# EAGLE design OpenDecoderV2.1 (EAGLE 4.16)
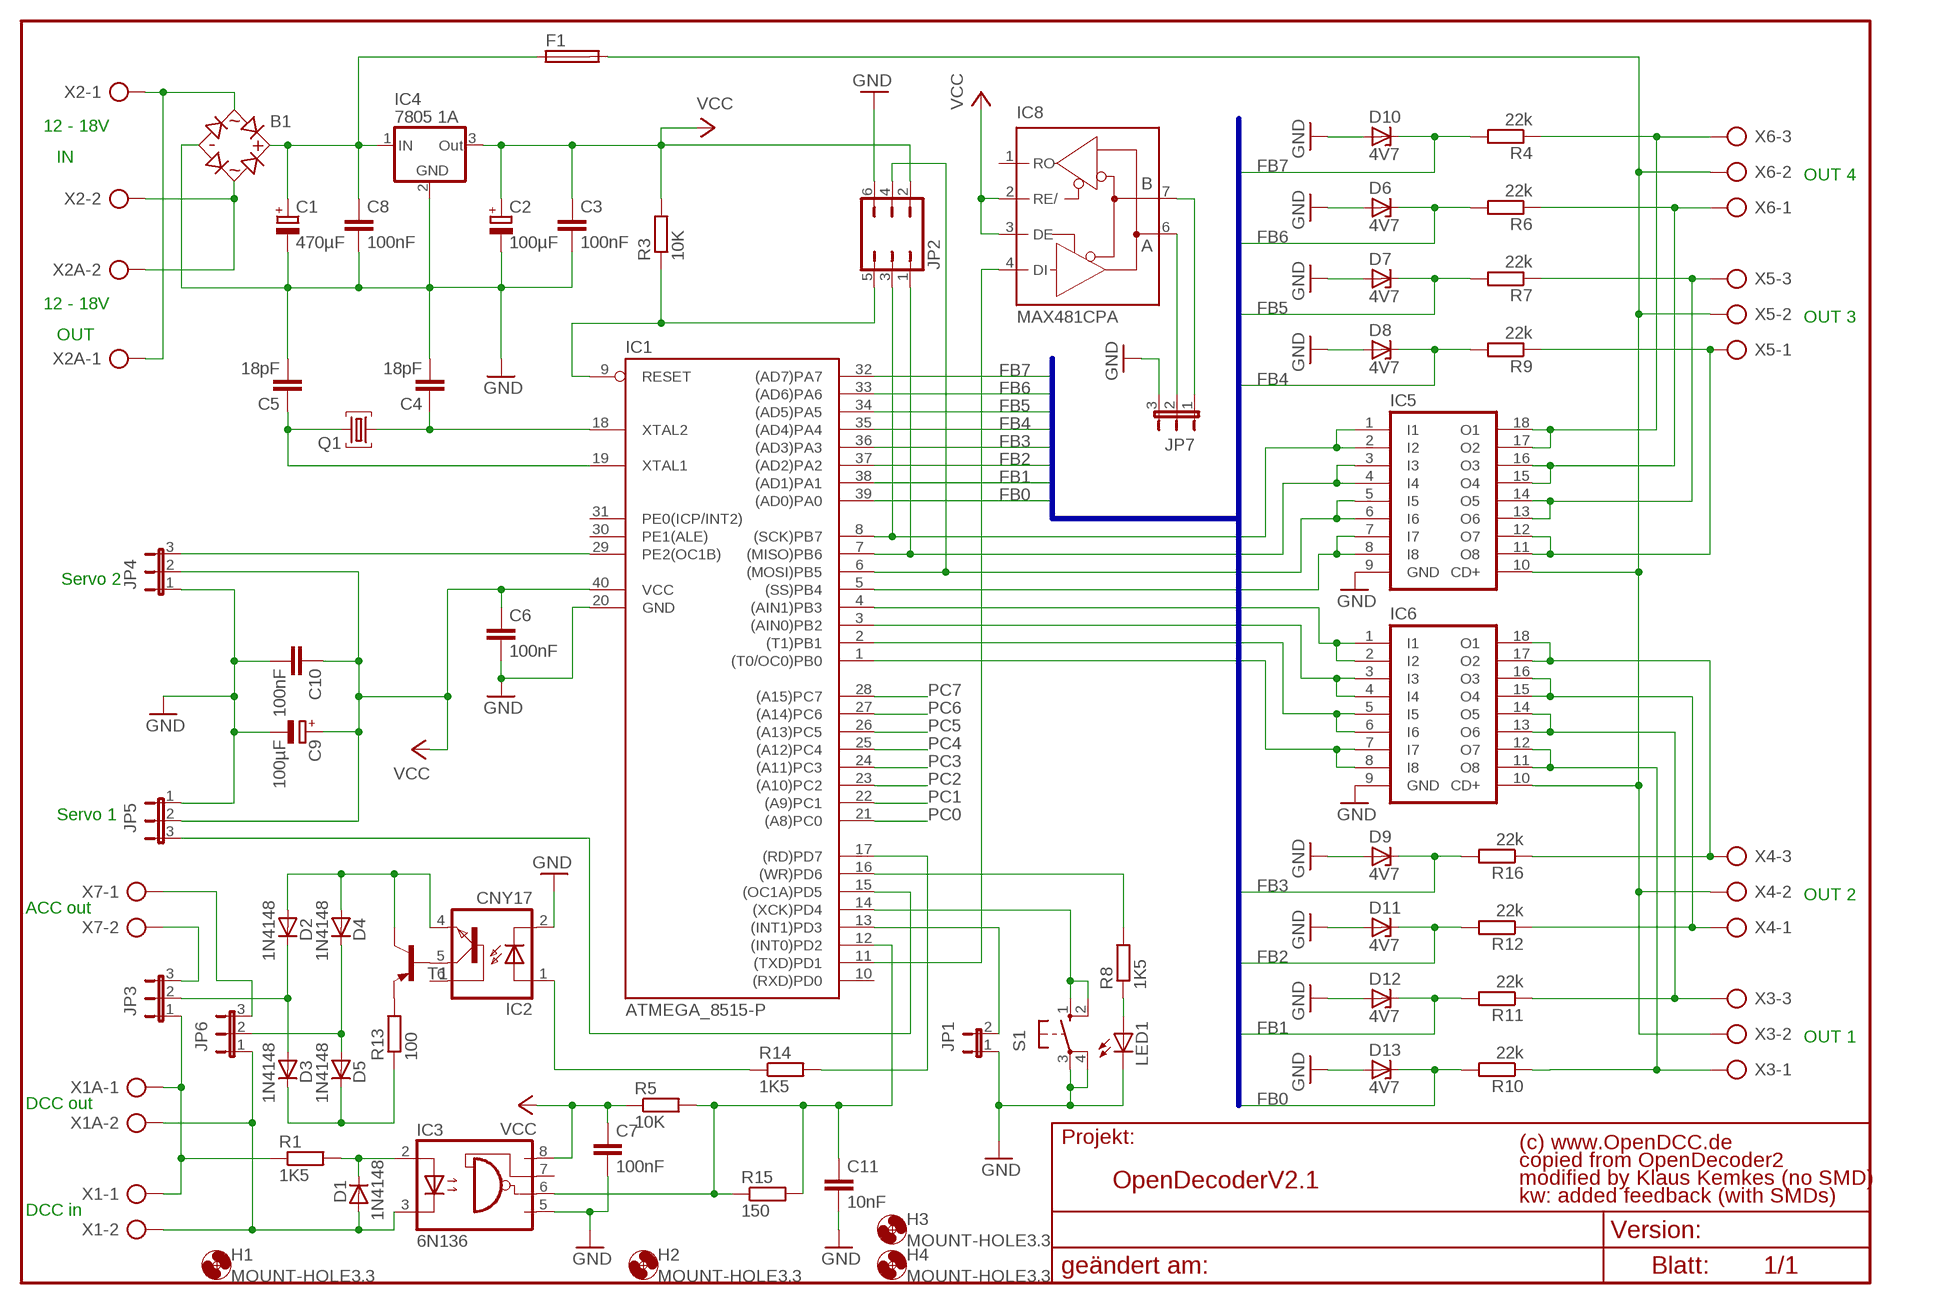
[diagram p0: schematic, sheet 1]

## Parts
B1  1,5A_RUND  [RB1A]
C1  470µF  ELKO-5-10.5-RADIAL  [R5-10,5]
C2  100µF  ELKO-2.5-7--RADIAL  [R2.5-7]
C3  100nF  KERAMIK5/4.5  [K5]
C4  18pF  KERAMIK2.5/4  [K2,5]
C5  18pF  KERAMIK2.5/4  [K2,5]
C6  100nF  KERAMIK5/4.5  [K5]
C7  100nF  KERAMIK5/4.5  [K5]
C8  100nF  KERAMIK5/4.5  [K5]
C9  100µF  ELKO-2.5-7--RADIAL  [R2.5-7]
C10  100nF  KERAMIK2.5/4  [K2,5]
C11  10nF  KERAMIK5/4.5  [K5]
D1  1N4148  1N414810MM  [DO35-10]
D2  1N4148  1N41487,5MM  [DO35-7]
D3  1N4148  1N41487,5MM  [DO35-7]
D4  1N4148  1N41487,5MM  [DO35-7]
D5  1N4148  1N41487,5MM  [DO35-7]
D6  4V7  ZENER-DIODESOD80C  [SOD80C]
D7  4V7  ZENER-DIODESOD80C  [SOD80C]
D8  4V7  ZENER-DIODESOD80C  [SOD80C]
D9  4V7  ZENER-DIODESOD80C  [SOD80C]
D10  4V7  ZENER-DIODESOD80C  [SOD80C]
D11  4V7  ZENER-DIODESOD80C  [SOD80C]
D12  4V7  ZENER-DIODESOD80C  [SOD80C]
D13  4V7  ZENER-DIODESOD80C  [SOD80C]
F1  TE5A  [TE5]
H1  MOUNT-HOLE3.3  [3,3]
H2  MOUNT-HOLE3.3  [3,3]
H3  MOUNT-HOLE3.3  [3,3]
H4  MOUNT-HOLE3.3  [3,3]
IC1  ATMEGA_8515-P  [DIL40]
IC2  CNY17  [DIL06]
IC3  6N136  6N137  [DIL08]
IC4  7805 1A  78S15  [TO220STEHEND]
IC5  ULN2803A  [DIL18]
IC6  ULN2803A  [DIL18]
IC8  MAX481CPA  [DIL08]
JP1  STIFTLEISTE_2POL  [STIFTLEISTE_2POL]
JP2  STIFTLEISTE_3POL_2REIHIG  [STIFTLEISTE_3POL_2REIHIG]
JP3  STIFTLEISTE_3POL  [STIFTLEISTE_3POL]
JP4  Servo2  STIFTLEISTE_3POL  [STIFTLEISTE_3POL]
JP5  Servo1  STIFTLEISTE_3POL  [STIFTLEISTE_3POL]
JP6  STIFTLEISTE_3POL  [STIFTLEISTE_3POL]
JP7  STIFTLEISTE_3POL  [STIFTLEISTE_3POL]
LED1  LED5MM  [LED5MM]
Q1  QUARZ  [2-POL]
R1  1K5  R1/2W10MM  [1/2W10MM]
R3  10K  R1/2W10MM  [1/2W10MM]
R4  22k  R-EU_R1206  [R1206]
R5  10K  R1/2W10MM  [1/2W10MM]
R6  22k  R-EU_R1206  [R1206]
R7  22k  R-EU_R1206  [R1206]
R8  1K5  R1/2W10MM  [1/2W10MM]
R9  22k  R-EU_R1206  [R1206]
R10  22k  R-EU_R1206  [R1206]
R11  22k  R-EU_R1206  [R1206]
R12  22k  R-EU_R1206  [R1206]
R13  100  R1/2W10MM  [1/2W10MM]
R14  1K5  R1/2W10MM  [1/2W10MM]
R15  150  R1/2W10MM  [1/2W10MM]
R16  22k  R-EU_R1206  [R1206]
S1  10-XX  [B3F-10XX]
T1  BC5575MM  [TO92_5MM]
X1  AK02RECHTS_5,08  [AK2FACH_RECHTS]
X1A  AK02RECHTS_5,08  [AK2FACH_RECHTS]
X2  AK02RECHTS_5,08  [AK2FACH_RECHTS]
X2A  AK02RECHTS_5,08  [AK2FACH_RECHTS]
X3  AK03RECHTS_5,08MM  [AK3FACH_RECHTS]
X4  AK03RECHTS_5,08MM  [AK3FACH_RECHTS]
X5  AK03RECHTS_5,08MM  [AK3FACH_RECHTS]
X6  AK03RECHTS_5,08MM  [AK3FACH_RECHTS]
X7  AK02RECHTS_5,08  [AK2FACH_RECHTS]

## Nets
FB0: D13.C IC1.39((AD0)PA0) R10.2
FB1: D12.C IC1.38((AD1)PA1) R11.2
FB2: D11.C IC1.37((AD2)PA2) R12.2
FB3: D9.C IC1.36((AD3)PA3) R16.2
FB4: D8.C IC1.35((AD4)PA4) R9.2
FB5: D7.C IC1.34((AD5)PA5) R7.2
FB6: D6.C IC1.33((AD6)PA6) R6.2
FB7: D10.C IC1.32((AD7)PA7) R4.2
GND: B1.- C1.- C2.- C3.2 C4.2 C5.2 C6.2 C7.2 C8.2 C9.- C10.2 C11.2 D6.A D7.A D8.A D9.A D10.A D11.A D12.A D13.A IC1.20(GND) IC2.2(C) IC3.5(GND) IC4.2(GND) IC5.9(GND) IC6.9(GND) JP1.1 JP2.6 JP4.1 JP5.1 JP7.3 LED1.K(C) S1.3(P) S1.4(P1)
N$1: D1.A IC3.3(C) JP6.1 X1.P2 X1A.P2
N$2: D1.C IC3.2(A) R1.2
N$3: JP3.1 R1.1 X1.P1 X1A.P1
N$4: B1.AC2 X2.P2 X2A.P2
N$5: D3.C D5.C R13.1
N$6: R13.2 T1.1(E)
N$7: D2.A D4.A IC2.4(EMI) T1.3(C)
N$8: IC2.5(COL) T1.2(B)
N$9: IC1.17((RD)PD7) R14.2
N$10: C11.1 IC1.12((INT0)PD2) IC3.6(VO) R5.2 R15.1 R15.2
N$11: B1.AC1 X2.P1 X2A.P1
N$12: B1.+ C1.+ C8.1 F1.1 IC4.1(VI)
N$13: C4.1 IC1.18(XTAL2) Q1.1
N$14: C5.1 IC1.19(XTAL1) Q1.2
N$15: IC1.13((INT1)PD3) JP1.2
N$16: IC1.9(RESET) JP2.5 R3.1
N$17: IC1.4((AIN1)PB3) IC6.1(I1) IC6.2(I2)
N$18: IC1.14((XCK)PD4) S1.1(S) S1.2(S1)
N$19: IC1.16((WR)PD6) R8.2
N$20: LED1.A R8.1
N$21: IC5.17(O2) IC5.18(O1) R4.1 X6.P3
N$22: IC1.3((AIN0)PB2) IC6.3(I3) IC6.4(I4)
N$23: IC1.7((MISO)PB6) IC5.3(I3) IC5.4(I4) JP2.1
N$24: IC1.6((MOSI)PB5) IC5.5(I5) IC5.6(I6) JP2.4
N$25: IC1.5((SS)PB4) IC5.7(I7) IC5.8(I8)
N$26: IC1.8((SCK)PB7) IC5.1(I1) IC5.2(I2) JP2.3
N$27: IC5.15(O4) IC5.16(O3) R6.1 X6.P1
N$28: IC1.2((T1)PB1) IC6.5(I5) IC6.6(I6)
N$29: IC1.1((T0/OC0)PB0) IC6.7(I7) IC6.8(I8)
N$30: IC5.13(O6) IC5.14(O5) R7.1 X5.P3
N$31: IC5.11(O8) IC5.12(O7) R9.1 X5.P1
N$32: F1.2 IC5.10(CD+) IC6.10(CD+) X3.P2 X4.P2 X5.P2 X6.P2
N$33: IC6.17(O2) IC6.18(O1) R16.1 X4.P3
N$34: IC6.15(O4) IC6.16(O3) R12.1 X4.P1
N$35: IC6.13(O6) IC6.14(O5) R11.1 X3.P3
N$36: IC6.11(O8) IC6.12(O7) R10.1 X3.P1
N$37: D4.C D5.A JP6.2
N$38: IC2.1(A) R14.1
N$39: IC1.15((OC1A)PD5) JP5.3
N$40: IC1.29(PE2(OC1B)) JP4.3
N$41: D2.C D3.A JP3.2
N$42: JP3.3 X7.P2
N$43: JP6.3 X7.P1
N$45: IC1.11((TXD)PD1) IC8.4(DI)
N$46: IC8.7(B) JP7.1
N$47: IC8.6(A) JP7.2
VCC: C2.+ C3.1 C6.1 C7.1 C9.+ C10.1 IC1.40(VCC) IC3.8(VCC) IC4.3(VO) IC8.2(RE/) IC8.3(DE) JP2.2 JP4.2 JP5.2 R3.2 R5.1
Unconnected: IC1.10((RXD)PD0) IC1.21((A8)PC0) IC1.22((A9)PC1) IC1.23((A10)PC2) IC1.24((A11)PC3) IC1.25((A12)PC4) IC1.26((A13)PC5) IC1.27((A14)PC6) IC1.28((A15)PC7) IC1.30(PE1(ALE)) IC1.31(PE0(ICP/INT2)) IC2.6(BAS) IC3.7(VE) IC8.1(RO)

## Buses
FB[0..7]

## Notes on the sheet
- 12 - 18V
- IN
- OUT 4
- 12 - 18V
- OUT 3
- OUT
- Servo 2
- Servo 1
- OUT 2
- ACC out
- OUT 1
- DCC out
- (c) www.OpenDCC.de
- copied from OpenDecoder2
- modified by Klaus Kemkes (no SMD)
- kw: added feedback (with SMDs)
- DCC in

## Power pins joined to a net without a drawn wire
GND: IC8.5(GND)
VCC: IC8.8(VCC)

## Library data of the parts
B1 = 11 Gleichrichter:1,5A_RUND: Gleichrichter Rund 1,5 A
C1 C2 C9 = 11 Kondensatoren:ELKO-: POLARIZED CAPACITOR, European symbol
C3-C8 C10 C11 = 11 Kondensatoren:KERAMIK: CAPACITOR
D1-D5 = 11 Dioden:1N4148: DIODE
D6-D13 = diode:ZENER-DIODE: Z-Diode
F1 = 11 Sicherungen:TE5: FUSE
H1-H4 = holes:MOUNT-HOLE: MOUNTING HOLE with drill center marker
IC1 = 11 Mikroprozessoren:ATMEGA_8515-P: MICROCONTROLLER 8 Kbytes FLASH 512 bytes SRAM 512 bytes EEPROM USART 8-channel 10 bit ADC Source: avr.lbr
IC2 = 11 Optokoppler:CNY17: SIEMENS OPTO COUPLER
IC3 = 11 Optokoppler:6N137: MOTOROLA OPTO COUPLER
IC4 = 11 Spannungsregler:78*: Positive VOLTAGE REGULATOR Source: http://cache.national.com/ds/LM/LM78L05.pdf http://www.fairchildsemi.com/ds/LM/LM7805.pdf
IC5 IC6 = 11 IC´s:ULN2803A: DRIVER ARRAY
IC8 = maxim:MAX481CPA: RS485 TRANSEIVER
JP1 = 11 Stecker Brücken usw:STIFTLEISTE_2POL: JUMPER
JP2 = 11 Stecker Brücken usw:STIFTLEISTE_3POL_2REIHIG
JP3-JP7 = 11 Stecker Brücken usw:STIFTLEISTE_3POL: JUMPER
LED1 = 11 Licht:LED: LED
Q1 = 11 Quarze Schwinger:QUARZ
R1 R3 R5 R8 R13-R15 = 11 Widerstände:R: RESISTOR, European symbol
R4 R6 R7 R9-R12 R16 = rcl:R-EU_: RESISTOR, European symbol
S1 = switch-omron:10-XX: OMRON SWITCH
T1 = 11 Transistoren:BC557
X1 X1A X2 X2A X7 = 11 Anschlußklemmen:AK02: CONNECTOR
X3-X6 = 11 Anschlußklemmen:AK03: CONNECTOR

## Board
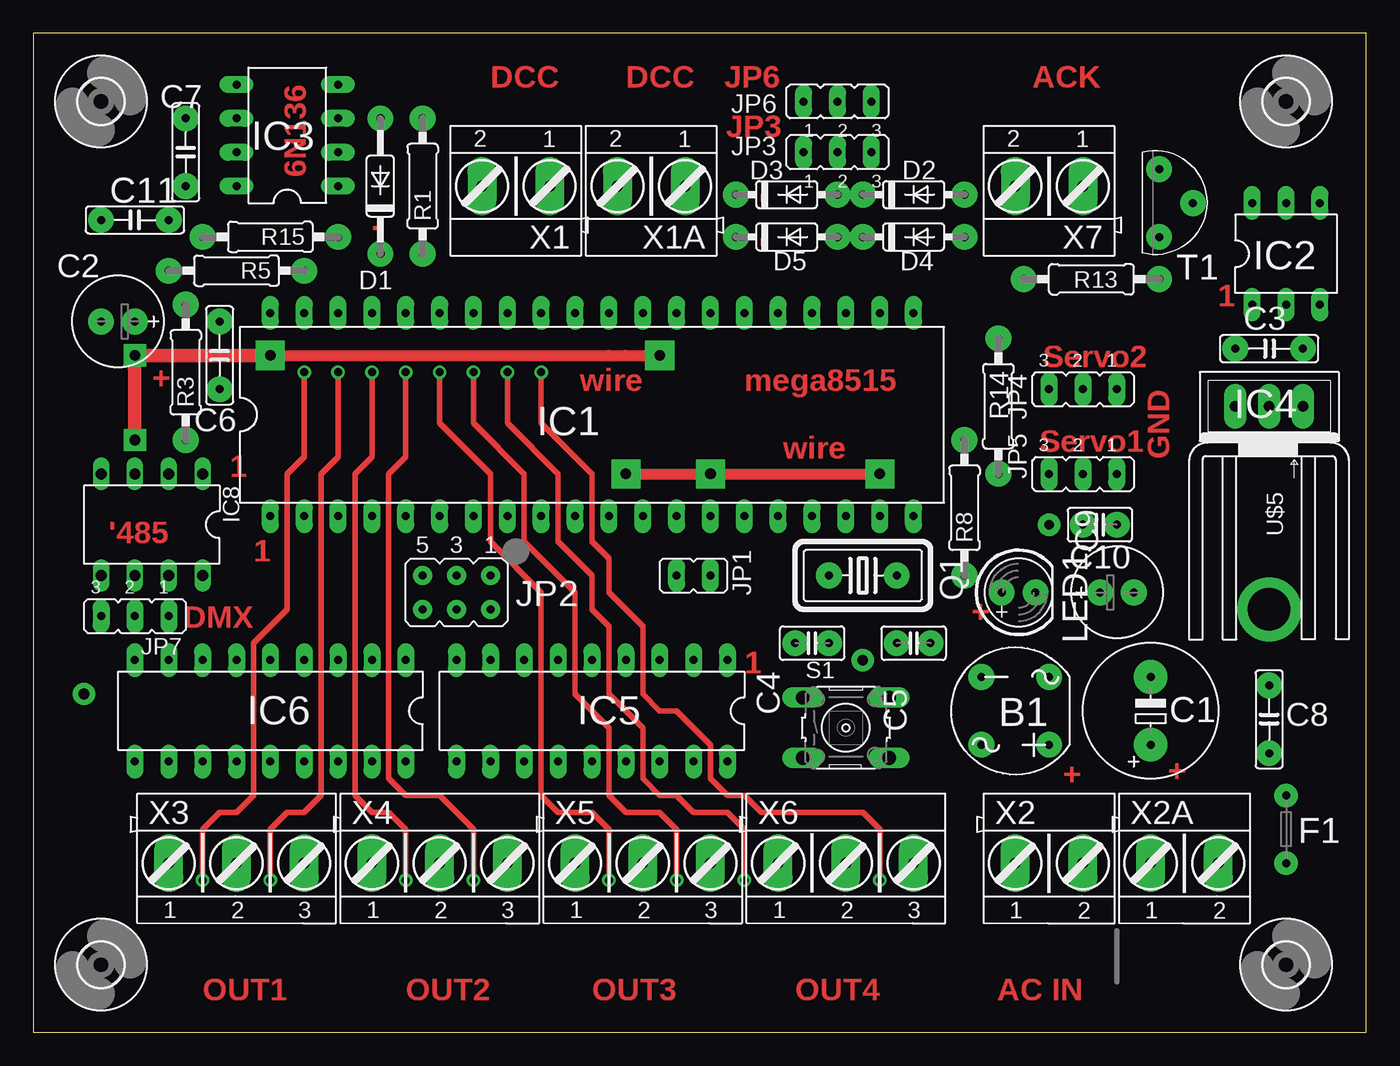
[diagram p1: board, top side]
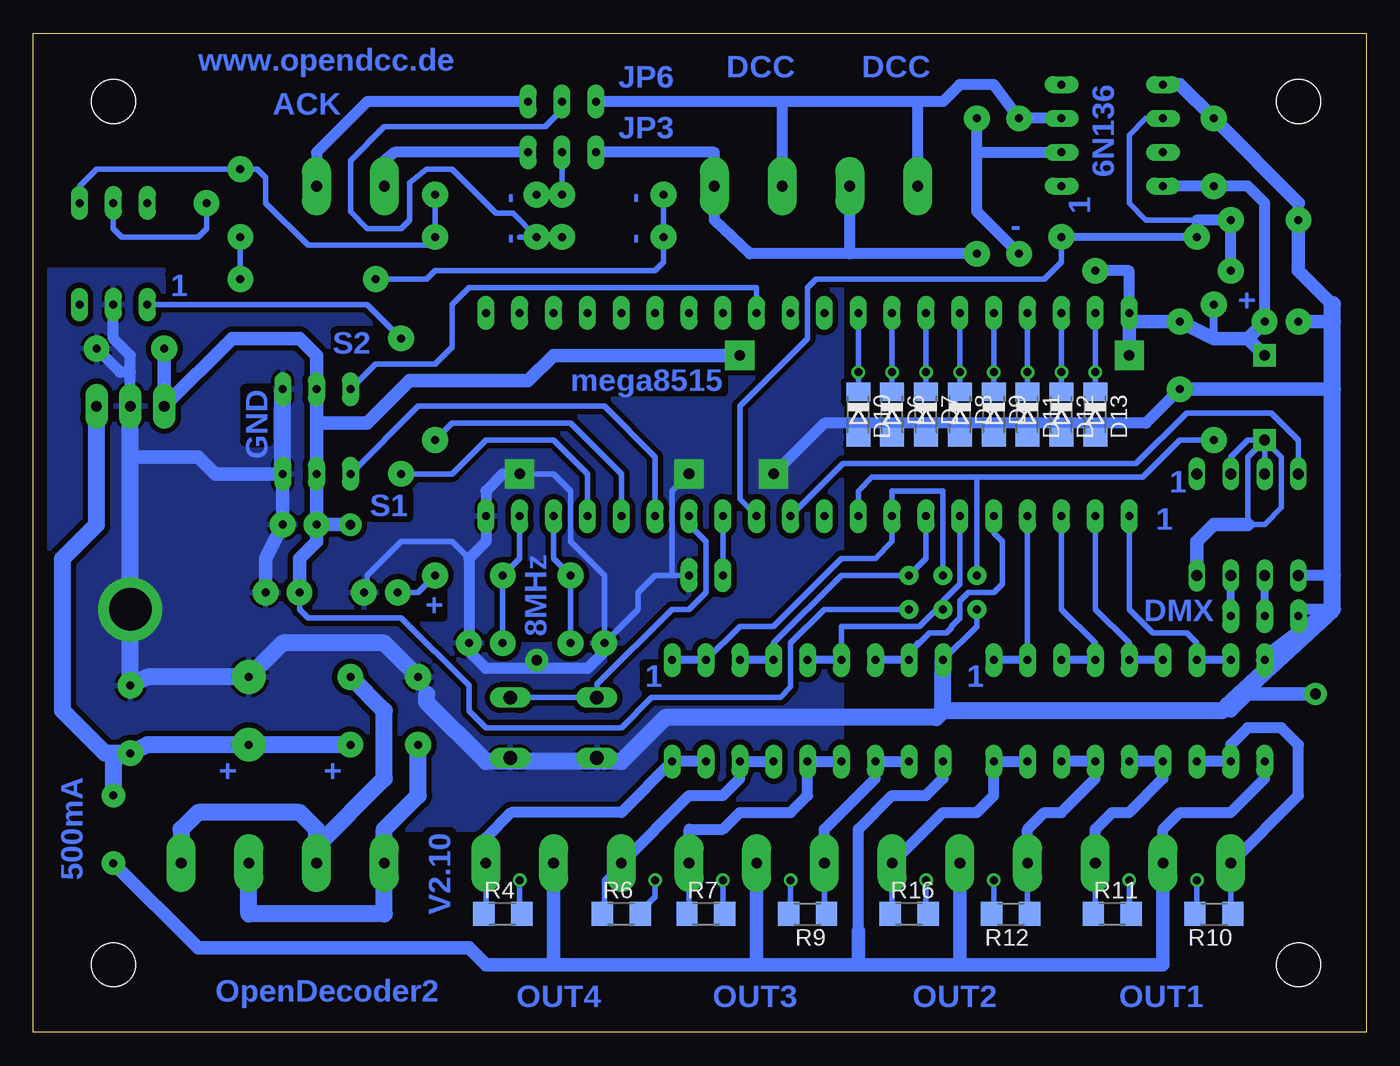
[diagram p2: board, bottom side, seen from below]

Size 99.99 x 74.96 mm. Coordinates in mm from the lower left corner, seen from the top.
Outline: 0.01,0 99.98,0 99.99,74.96 0,74.96 0.01,0
Copper layers (1*16): Top 0.035mm / dielectric 1.5mm / Bottom 0.035mm
Design rules "zwilling": minimum track width 10mil, minimum drill 20mil, track to track 8mil, track to pad 8mil, pad to pad 8mil, via to via 8mil, smd to smd 8mil, copper to edge 40mil, drill to drill 8mil, minimum pad ring 8mil, minimum via ring 8mil, stop-mask expansion 6mil, vias tented up to drill 0mil, thermal gap 10mil

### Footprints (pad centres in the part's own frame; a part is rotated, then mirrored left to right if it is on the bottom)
RB1A = drill 0.6 pad 1.93 round: + -2.54,2.54; - 2.54,-2.54; AC1 2.54,2.54; AC2 -2.54,-2.54
R5-10,5 = drill 0.6 pad 2.54 round: + -2.54,0; - 2.54,0
R2.5-7 = drill 0.6 pad 1.93 round: + 0,0; - 2.54,0
K5 = drill 0.6 pad 1.93 round: 1 -2.54,0; 2 2.54,0
K2,5 = drill 0.6 pad 1.93 round: 1 -2.54,0; 2 0,0
DO35-10 = drill 0.6 pad 1.93 round: A 5.08,0; C -5.08,0
DO35-7 = drill 0.6 pad 1.93 round: A 3.81,0; C -3.81,0
SOD80C = smd 1.4 x 1.8: A 1.7,0; C -1.7,0
TE5 = drill 0.6 pad 1.778 round: 1 -2.54,0; 2 2.54,0
3,3 = hole 3.3: 0,0
DIL40 = drill 0.6 pad 1.27 long: 1 -24.13,-7.62; 2 -21.59,-7.62; 3 -19.05,-7.62; 4 -16.51,-7.62; 5 -13.97,-7.62; 6 -11.43,-7.62; 7 -8.89,-7.62; 8 -6.35,-7.62; 9 -3.81,-7.62; 10 -1.27,-7.62; 11 1.27,-7.62; 12 3.81,-7.62; 13 6.35,-7.62; 14 8.89,-7.62; 15 11.43,-7.62; 16 13.97,-7.62; 17 16.51,-7.62; 18 19.05,-7.62; 19 21.59,-7.62; 20 24.13,-7.62; 21 24.13,7.62; 22 21.59,7.62; 23 19.05,7.62; 24 16.51,7.62; 25 13.97,7.62; 26 11.43,7.62; 27 8.89,7.62; 28 6.35,7.62; 29 3.81,7.62; 30 1.27,7.62; 31 -1.27,7.62; 32 -3.81,7.62; 33 -6.35,7.62; 34 -8.89,7.62; 35 -11.43,7.62; 36 -13.97,7.62; 37 -16.51,7.62; 38 -19.05,7.62; 39 -21.59,7.62; 40 -24.13,7.62
DIL06 = drill 0.6 pad 1.27 long: 1 -2.54,-3.81; 2 0,-3.81; 3 2.54,-3.81; 4 2.54,3.81; 5 0,3.81; 6 -2.54,3.81
DIL08 = drill 0.6 pad 1.27 long: 1 -3.81,-3.81; 2 -1.27,-3.81; 3 1.27,-3.81; 4 3.81,-3.81; 5 3.81,3.81; 6 1.27,3.81; 7 -1.27,3.81; 8 -3.81,3.81
TO220STEHEND = drill 0.8 pad 1.676 long: 1 -2.54,0; 2 0,0; 3 2.54,0
DIL18 = drill 0.6 pad 1.27 long: 1 -10.16,-3.81; 2 -7.62,-3.81; 3 -5.08,-3.81; 4 -2.54,-3.81; 5 0,-3.81; 6 2.54,-3.81; 7 5.08,-3.81; 8 7.62,-3.81; 9 10.16,-3.81; 10 10.16,3.81; 11 7.62,3.81; 12 5.08,3.81; 13 2.54,3.81; 14 0,3.81; 15 -2.54,3.81; 16 -5.08,3.81; 17 -7.62,3.81; 18 -10.16,3.81
DIL08' = drill 0.813 long: 1 -3.81,-3.81; 2 -1.27,-3.81; 3 1.27,-3.81; 4 3.81,-3.81; 5 3.81,3.81; 6 1.27,3.81; 7 -1.27,3.81; 8 -3.81,3.81
STIFTLEISTE_2POL = drill 0.6 pad 1.27 long: 1 -1.27,0; 2 1.27,0
STIFTLEISTE_3POL_2REIHIG = drill 0.6 pad 1.422 round: 1 -2.54,0; 2 -2.54,2.54; 3 0,0; 4 0,2.54; 5 2.54,0; 6 2.54,2.54
STIFTLEISTE_3POL = drill 0.6 pad 1.27 long: 1 -2.54,0; 2 0,0; 3 2.54,0
LED5MM = drill 0.6 pad 1.93 round: A -2.54,0; K 0,0
2-POL = drill 0.6 pad 1.93 round: 1 -2.54,0; 2 2.54,0
1/2W10MM = drill 0.6 pad 1.93 round: 1 -5.08,0; 2 5.08,0
R1206 = smd 1.6 x 1.803: 1 -1.422,0; 2 1.422,0
B3F-10XX = drill 1.016 long: 1 -3.251,2.261; 2 3.251,2.261; 3 -3.251,-2.261; 4 3.251,-2.261
TO92_5MM = drill 0.6 pad 1.93 round: 1 2.54,0; 2 0,2.54; 3 -2.54,0
AK2FACH_RECHTS = drill 0.8 pad 2.184 long: P1 -5.08,0; P2 0,0
AK3FACH_RECHTS = drill 0.8 pad 2.184 long: P1 -5.08,0; P2 0,0; P3 5.08,0

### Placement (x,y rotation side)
B1  73.66,24.13 180 top
C1  83.82,24.13 90 top
C2  7.62,53.34 180 top
C3  92.71,51.31 0 top
C4  57.15,29.21 180 top
C5  67.31,29.21 0 top
C6  13.97,50.8 270 top
C7  11.43,66.04 90 top
C8  92.71,23.49 90 top
C9  80.03,33.01 0 top
C10  81.28,38.1 0 top
C11  7.62,60.96 180 top
D1  26.04,63.5 90 top
D2  66.04,62.86 0 top
D3  56.52,62.86 0 top
D4  66.04,59.69 0 top
D5  56.52,59.69 0 top
D6  35.56,46.35 270 bottom
D7  33.02,46.35 270 bottom
D8  30.48,46.35 270 bottom
D9  27.94,46.35 270 bottom
D10  38.1,46.35 270 bottom
D11  25.4,46.35 270 bottom
D12  22.86,46.35 270 bottom
D13  20.32,46.35 270 bottom
F1  93.98,15.24 270 top
H1  5.08,5.08 0 top
H2  93.98,5.08 0 top
H3  5.08,69.85 0 top
H4  93.98,69.85 0 top
IC1  41.91,46.35 0 top
IC2  93.98,58.42 0 top
IC3  19.05,67.31 90 top
IC4  92.71,46.99 180 top
IC5  41.91,24.13 180 top
IC6  17.78,24.13 180 top
IC8  MAX481CPA  [DIL08']  8.89,38.1 180 top
JP1  49.53,34.29 180 top
JP2  31.75,34.29 180 top
JP3  60.33,66.04 0 top
JP4  78.74,48.26 180 top
JP5  78.74,41.91 180 top
JP6  60.33,69.85 0 top
JP7  7.62,31.24 180 top
LED1  75.18,33.02 0 top
Q1  62.23,34.29 0 top
R1  29.21,63.5 90 top
R3  11.43,49.53 90 top
R4  64.77,8.89 0 bottom
R5  15.24,57.15 180 top
R6  55.88,8.89 0 bottom
R7  49.53,8.89 0 bottom
R8  69.85,39.37 90 top
R9  41.91,8.89 180 bottom
R10  11.43,8.89 180 bottom
R11  19.05,8.89 0 bottom
R12  26.67,8.89 180 bottom
R13  79.38,56.51 0 top
R14  72.39,46.99 270 top
R15  17.78,59.69 180 top
R16  34.29,8.89 0 bottom
S1  60.96,22.86 0 top
T1  84.46,62.23 270 top
U$5  [78XX]  92.71,44.45 180 top
X1  33.66,63.5 180 top
X1A  43.82,63.5 180 top
X2  78.74,12.7 0 top
X2A  88.9,12.7 0 top
X3  15.24,12.7 0 top
X4  30.48,12.7 0 top
X5  45.72,12.7 0 top
X6  60.96,12.7 0 top
X7  73.66,63.5 180 top

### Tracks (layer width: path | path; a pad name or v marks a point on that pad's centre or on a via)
FB0  (via drill 0.6)
  Top 0.406: v20.32,49.53 20.32,43.18 19.05,41.91 19.05,31.75 16.51,29.21 16.51,17.78 15.24,16.51 13.97,16.51 12.7,15.24 v12.7,11.43
  Bottom 0.406: D13.C v20.32,49.53 IC1.39 | R10.2 12.7,8.89 v12.7,11.43
FB1  (via drill 0.6)
  Top 0.406: v22.86,49.53 22.86,43.18 21.59,41.91 21.59,17.78 20.32,16.51 19.05,16.51 17.78,15.24 v17.78,11.43
  Bottom 0.406: D12.C v22.86,49.53 IC1.38 | R11.2 17.78,8.89 v17.78,11.43
FB2  (via drill 0.6)
  Top 0.406: v25.4,49.53 25.4,43.18 24.13,41.91 24.13,17.78 25.4,16.51 26.67,16.51 27.94,15.24 v27.94,11.43
  Bottom 0.406: D11.C v25.4,49.53 IC1.37 | R12.2 27.94,8.89 v27.94,11.43
FB3  (via drill 0.6)
  Top 0.406: v27.94,49.53 27.94,43.18 26.67,41.91 26.67,19.05 27.94,17.78 30.48,17.78 33.02,15.24 v33.02,11.43
  Bottom 0.406: D9.C v27.94,49.53 IC1.36 | R16.2 33.02,8.89 v33.02,11.43
FB4  (via drill 0.6)
  Top 0.406: v30.48,49.53 30.48,45.72 34.29,41.91 34.29,36.83 38.1,33.02 38.1,17.78 39.37,16.51 41.91,16.51 43.18,15.24 v43.18,11.43
  Bottom 0.406: D8.C v30.48,49.53 IC1.35 | R9.2 43.18,8.89 v43.18,11.43
FB5  (via drill 0.6)
  Top 0.406: v33.02,49.53 33.02,45.72 36.83,41.91 36.83,36.83 40.64,33.02 40.64,25.4 43.18,22.86 43.18,17.78 44.45,16.51 46.99,16.51 48.26,15.24 v48.26,11.43
  Bottom 0.406: D7.C v33.02,49.53 IC1.34 | R7.2 48.26,8.89 v48.26,11.43
FB6  (via drill 0.6)
  Top 0.406: v35.56,49.53 35.56,45.72 39.37,41.91 39.37,36.83 41.91,34.29 41.91,31.75 43.18,30.48 43.18,25.4 45.72,22.86 45.72,19.05 46.99,17.78 48.26,17.78 49.53,16.51 52.07,16.51 53.34,15.24 v53.34,11.43
  Bottom 0.406: D6.C v35.56,49.53 IC1.33 | v53.34,11.43 53.34,10.16 54.61,8.89 R6.2
FB7  (via drill 0.6)
  Top 0.406: v38.1,49.53 38.1,45.72 41.91,41.91 41.91,36.83 43.18,35.56 43.18,33.02 45.72,30.48 45.72,25.4 46.99,24.13 48.26,24.13 50.8,21.59 50.8,19.05 52.07,17.78 53.34,17.78 54.61,16.51 62.23,16.51 63.5,15.24 v63.5,11.43
  Bottom 0.406: D10.C v38.1,49.53 IC1.32 | R4.2 63.5,8.89 v63.5,11.43
GND  (via drill 0.8 pad 1.68, 0.8 pad 2.18, 3.2 pad 3.81)
  Top 0.813: v44.45,41.91 v63.5,41.91
  Bottom 0.406: JP2.6 29.21,30.48 IC5.9 | 52.07,34.29 53.34,34.29 54.61,33.02 54.61,31.75 C4.2 57.15,34.29 59.69,36.83 59.69,40.64 60.96,41.91 v63.5,41.91 | 52.07,34.29 JP1.1 | 66.04,38.1 IC1.20 | v50.8,41.91 52.07,40.64 52.07,34.29 | S1.3 57.43,20.6 57.15,20.32 | S1.4 64.49,20.6 66.04,20.32 | 25.4,45.72 D11.A | 27.94,45.72 D9.A | 30.48,45.72 D8.A | 33.02,45.72 D7.A | 35.56,45.72 D6.A | 22.86,45.72 D12.A | 38.1,45.72 D10.A | 20.32,45.72 D13.A | LED1.K 74.93,33.27 74.93,34.29 72.39,36.83 68.58,36.83 67.31,35.56
  Bottom 0.813: C11.2 5.08,62.23 | 70.49,25.4 B1.- | C4.2 57.15,28.57 58.42,27.3 66.04,27.3 67.31,28.57 C5.2 67.31,35.56 66.04,36.83 66.04,38.1 66.04,40.64 64.77,41.91 v63.5,41.91 | v44.45,41.91 40.64,45.72 38.1,45.72 35.56,45.72 33.02,45.72 30.48,45.72 27.94,45.72 25.4,45.72 22.86,45.72 20.32,45.72 16.51,45.72 C6.2 | IC2.2 93.98,52.07 92.71,50.8 92.71,49.53 | IC4.2 92.71,49.53 | C3.2 93.47,49.53 92.71,49.53 | 2.54,34.29 IC8.5 | JP7.3 4.57,31.75 2.54,31.75
  Bottom 1.016: C9.- 82.57,35.54 C10.2 JP5.1 86.36,41.91 87.63,43.18 92.71,43.18 | IC3.5 13.97,71.12 C7.2 5.08,62.23 | C11.2 5.08,57.15 2.54,54.61 | 2.54,53.34 C2.- | 2.54,48.26 C6.2 | 10.45,24.45 10.45,24.42 10.16,24.13 8.89,25.4 v3.81,25.4
  Bottom 1.27: 31.75,24.13 IC5.9 | 31.75,24.13 10.8,24.13 10.45,24.45 2.54,31.75 | 31.75,24.13 32.26,23.62 52.58,23.62 55.88,20.32 57.15,20.32 66.04,20.32 70.49,24.76 70.49,25.4 | 2.54,31.75 IC6.9 | 2.54,31.75 2.54,34.29 2.54,48.26 2.54,53.34 2.54,54.61 | B1.- 73.66,29.21 81.28,29.21 C1.- 91.44,26.67 C8.2 v92.71,31.75 92.71,43.18 IC4.2 | JP5.1 JP4.1
  other vias: 62.23,27.94
  pour Bottom (isolate 0.406): 39.37,57.15 99.06,57.15 99.06,15.24 39.37,15.24
N$1
  Bottom 0.813: IC3.3 D1.A 27.94,71.12 30.48,71.12 31.75,69.85 33.66,69.85 | 33.66,69.85 X1.P2 | 33.66,69.85 43.82,69.85 | 43.82,69.85 X1A.P2 | 43.82,69.85 JP6.1
N$2
  Bottom 0.813: 29.21,66.04 IC3.2 | D1.C 29.21,61.59 29.21,66.04 | 29.21,66.04 R1.2
N$3
  Bottom 0.813: R1.1 38.74,58.42 | 38.74,58.42 X1.P1 | 38.74,58.42 46.23,58.42 48.9,60.96 X1A.P1 48.9,66.04 JP3.1
N$4
  Bottom 1.27: X2A.P2 88.9,15.24 87.63,16.51 80.01,16.51 78.74,15.24 X2.P2 78.74,13.97 73.66,19.05 73.66,24.13 B1.AC2
N$5
  Bottom 0.406: D3.C D5.C 52.71,57.78 53.34,57.15 69.85,57.15 70.49,56.51 R13.1
N$6
  Bottom 0.406: R13.2 T1.1
N$7
  Bottom 0.406: D2.A D4.A 70.49,59.05 79.38,59.05 82.55,62.23 82.55,64.13 83.19,64.77 T1.3 95.25,64.77 96.52,63.5 IC2.4
N$8
  Bottom 0.406: T1.2 87,60.32 87.63,59.69 93.35,59.69 93.98,60.32 IC2.5
N$9
  Bottom 0.406: IC1.17 58.42,41.91 60.96,44.45 66.04,44.45 68.58,41.91 R14.2
N$10
  Bottom 0.406: R15.1 22.86,57.78 24.13,56.51 41.28,56.51 41.91,55.88 41.91,52.07 46.99,46.99 46.99,40 IC1.12 | 12.7,60.96 16.51,60.96 17.78,62.23 17.78,67.31 16.51,68.58 IC3.6
  Bottom 0.61: R15.2 R15.1
  Bottom 0.813: R5.2 C11.1 12.7,60.96 R15.2
N$11
  Bottom 1.27: X2A.P1 83.82,8.89 73.66,8.89 X2.P1 73.66,15.24 71.12,17.78 B1.AC1
N$12
  Bottom 1.27: B1.+ C1.+ 91.44,21.59 C8.1 | C8.1 94.62,20.95 97.79,24.13 97.79,35.56 95.25,38.1 IC4.1 | C8.1 93.35,20.95 93.98,20.32 F1.1
N$13
  Bottom 0.406: IC1.18 60.96,35.56 Q1.1 C4.1
N$14
  Bottom 0.406: IC1.19 63.5,35.56 Q1.2 C5.1
N$15
  Bottom 0.406: JP1.2 IC1.13
N$16
  Bottom 0.406: 29.21,41.65 JP2.5 | IC1.9 38.1,40.64 37.08,41.65 29.21,41.65 | R3.1 13.97,44.45 16.76,41.65 29.21,41.65
N$17
  Bottom 0.406: IC6.2 IC1.4
  Bottom 0.61: IC6.2 IC6.1
N$18
  Bottom 0.406: IC1.14 50.8,38.1 49.53,36.83 49.53,33.02 50.8,31.75 52.07,31.75 57.68,26.14 S1.1 65.51,25.12 | 65.51,25.12 S1.2 | 65.51,25.12 65.53,25.14
N$19
  Bottom 0.406: IC1.16 55.88,41.91 59.69,45.72 68.58,45.72 R8.2
N$20
  Bottom 0.406: LED1.A 71.12,33.02 R8.1
N$21
  Bottom 0.406: R4.1 66.04,8.89 X6.P3
  Bottom 0.813: IC5.17 IC5.18 55.88,16.51 64.14,16.51 66.04,14.6 X6.P3
N$22
  Bottom 0.406: IC6.4 20.32,29.21 22.86,31.75 IC1.3
  Bottom 0.61: IC6.4 IC6.3
N$23
  Bottom 0.406: IC1.7 33.02,35.56 JP2.1 39.37,34.29 44.45,29.21 IC5.4
  Bottom 0.61: IC5.4 IC5.3
N$24
  Bottom 0.406: IC1.6 30.48,33.65 31.75,32.38 JP2.4 32.26,31.75 33.53,30.48 39.37,30.48 IC5.6
  Bottom 0.61: IC5.6 IC5.5
N$25
  Bottom 0.406: IC1.5 27.94,37.46 27.31,36.83 27.31,33.65 27.94,33.02 29.85,33.02 30.48,32.38 30.48,31.11 31.12,30.48 31.12,30.35 31.5,29.97 32.77,29.97 34.04,28.7 33.66,29.21 IC5.8
  Bottom 0.61: IC5.8 IC5.7
N$26
  Bottom 0.406: IC5.2 46.99,30.48 44.45,30.48 39.37,35.56 36.83,35.56 35.56,36.83 IC1.8 35.56,40.64 31.75,40.64 JP2.3
  Bottom 0.61: IC5.2 IC5.1
N$27
  Bottom 0.406: R6.1 57.15,8.89 57.15,11.43 X6.P1
  Bottom 0.813: IC5.15 IC5.16 46.99,19.05 48.26,17.78 50.8,17.78 X6.P1
N$28
  Bottom 0.406: IC1.2 20.32,31.75 17.78,29.21 IC6.5
  Bottom 0.61: IC6.6 IC6.5
N$29
  Bottom 0.406: IC1.1 17.78,31.75 16,29.97 13.46,29.97 12.7,29.21 IC6.7
  Bottom 0.61: IC6.8 IC6.7
N$30
  Bottom 0.406: R7.1 50.8,8.89 X5.P3
  Bottom 0.813: IC5.13 IC5.14 41.91,17.78 43.18,16.51 46.99,16.51 48.26,15.24 50.8,15.24 X5.P3
N$31
  Bottom 0.406: R9.1 40.64,8.89 X5.P1
  Bottom 0.813: IC5.11 IC5.12 36.83,19.05 40.64,15.24 X5.P1
N$32
  Bottom 0.813: IC6.10 7.62,19.05 10.16,16.51 13.97,16.51 15.24,15.24 X3.P2 15.24,7.62 | 38.1,7.62 38.1,15.24 35.56,17.78 33.02,17.78 31.75,19.05 IC5.10
  Bottom 1.016: F1.2 87.63,6.35 67.31,6.35 66.04,5.08 60.96,5.08 | 30.48,5.08 15.24,5.08 X3.P2 | 30.48,5.08 38.1,5.08 | 38.1,5.08 45.72,5.08 | 45.72,5.08 60.96,5.08 | 60.96,5.08 X6.P2 | 45.72,5.08 X5.P2 | 30.48,5.08 X4.P2 | 38.1,5.08 38.1,7.62
N$33
  Bottom 0.406: R16.1 35.56,8.89 X4.P3
  Bottom 0.813: IC6.17 IC6.18 27.94,17.78 29.21,16.51 31.75,16.51 X4.P3
N$34
  Bottom 0.406: R12.1 25.4,8.89 X4.P1
  Bottom 0.813: IC6.16 IC6.15 20.32,19.05 22.86,16.51 24.13,16.51 25.4,15.24 X4.P1
N$35
  Bottom 0.406: R11.1 20.32,8.89 X3.P3
  Bottom 0.813: IC6.14 IC6.13 15.24,19.05 17.78,16.51 19.05,16.51 20.32,15.24 X3.P3
N$36
  Bottom 0.406: R10.1 10.16,8.89 X3.P1
  Bottom 0.813: IC6.12 IC6.11 10.16,21.59 8.89,22.86 6.35,22.86 5.08,21.59 5.08,17.78 X3.P1
N$37
  Bottom 0.406: D4.C D5.A D4.C | D4.C 63.5,59.69 | D4.C 64.01,61.47 65.28,61.47 68.58,64.77 70.49,64.77 71.76,63.75 71.76,60.96 72.39,60.32 74.93,60.32 76.2,61.59 76.2,65.4 73.66,67.94 61.6,67.94 60.33,69.21 JP6.2
N$38
  Bottom 0.406: R14.1 74.93,54.61 IC2.1
N$39
  Bottom 0.406: IC1.15 53.34,43.18 57.15,46.99 71.12,46.99 JP5.3
N$40
  Bottom 0.406: IC1.29 45.72,55.88 67.31,55.88 68.58,54.61 68.58,51.43 69.85,50.16 74.3,50.16 JP4.3
N$41
  Bottom 0.406: JP3.2 D3.A D2.C
N$42
  Bottom 0.813: JP3.3 72.9,66.04 73.66,65.4 X7.P2
N$43
  Bottom 0.813: JP6.3 74.93,69.85 78.74,66.04 X7.P1
N$45
  Bottom 0.406: IC1.11 39.24,42.67 17.27,42.67 13.46,46.48 7.11,46.48 5.08,44.45 IC8.4
N$46
  Bottom 0.61: JP7.1 IC8.7
N$47
  Bottom 0.61: JP7.2 IC8.6
VCC  (via drill 0.7 pad 1.68, 0.8 pad 1.68, 0.8 pad 2.18)
  Top 0.813: v17.78,50.8 43.18,50.8 | 43.18,50.8 44.45,50.8 | 43.18,50.8 v46.99,50.8
  Top 1.016: v7.62,44.45 v7.62,50.8 v17.78,50.8
  Bottom 0.406: JP2.2 40.64,31.75 43.18,29.21 43.18,25.91 43.94,25.14 53.59,25.14 55.88,22.86 66.04,22.86 67.31,24.13 67.31,26.03 72.39,31.11 79.38,31.11 80.02,31.74 C9.+ | 80.01,35.56 80.03,35.56 | IC8.2 10.16,43.18 8.89,44.45 v7.62,44.45 | v7.62,44.45 6.35,43.18 6.35,39.37 7.62,38.1 8.89,38.1 8.89,43.18 v7.62,44.45 | v7.62,44.45 IC8.3
  Bottom 0.61: 11.43,52.07 R3.2
  Bottom 0.813: IC3.8 C7.1 8.89,63.5 7.62,62.23 C2.+ | R5.1 17.78,57.15 IC1.40
  Bottom 1.016: 78.74,45.72 JP5.2 C10.1 | 78.74,45.72 JP4.2 78.74,50.8 80.01,52.07 85.09,52.07 IC4.3 C3.1 | 80.03,35.56 C9.+ | C10.1 78.74,36.83 80.01,35.56 | 78.74,45.72 74.93,45.72 71.76,48.89 62.87,48.89 60.96,50.8 v46.99,50.8 | 17.78,53.34 IC1.40 | 8.89,52.07 11.43,52.07 C6.1 17.78,53.34 | 8.89,52.07 C2.+ | v17.78,50.8 17.78,53.34 | 8.89,38.1 11.43,38.1 12.7,36.83 IC8.8 | v7.62,50.8 8.89,52.07 | C10.1 v76.2,38.1

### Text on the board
Top: 6N136 | DCC | DCC | JP6 | ACK | JP3 | - | - | - | - | - | 1 | Servo2 | wire | mega8515 | + | GND | wire | Servo1 | 1 | '485 | 1 | DMX | + | 1 | + | + | OUT1 | OUT2 | OUT3 | OUT4 | AC IN
Bottom: DCC | DCC | www.opendcc.de | 6N136 | JP6 | ACK | JP3 | 1 | - | - | - | - | - | 1 | + | S2 | mega8515 | GND | 1 | S1 | 1 | DMX | + | 8MHz | 1 | 1 | + | + | V2.10 | 500mA | OUT1 | OUT2 | OUT3 | OUT4 | OpenDecoder2
tDocu: OUT | IN | OUT | DCC | DCC | ACK | Servo 2 | Servo 1 | GND | GND | AC IN | AC OUT | OUT 1 | OUT 2 | OUT 3 | OUT 4 | 12 - 18V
